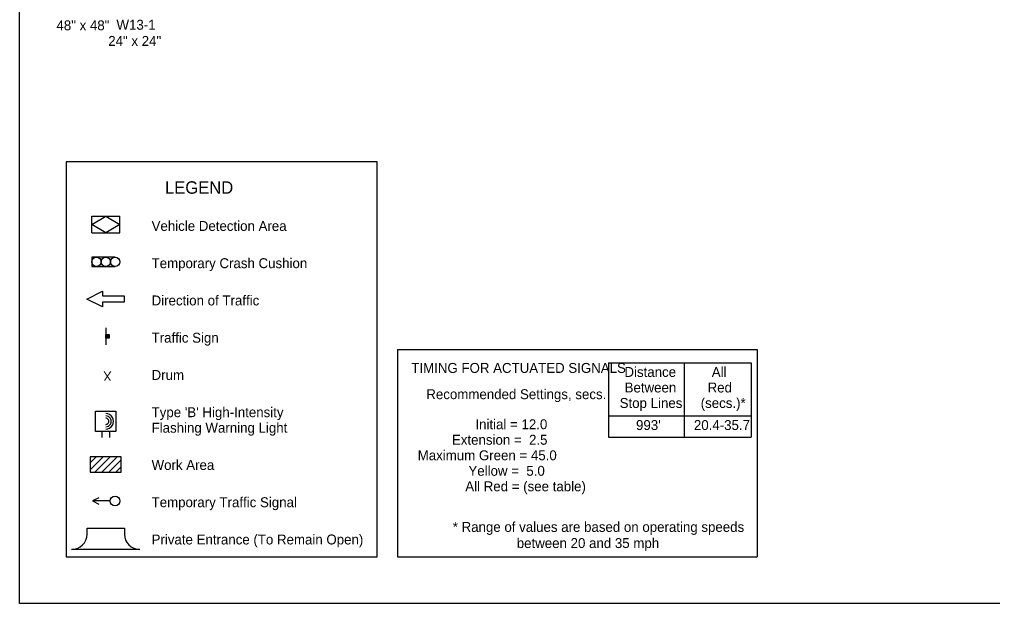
# Model space of a CAD drawing. Extents: x -2134934 to -2127057, y -2139046 to -2137036.
# Drawn here: x -2134934 to -2133366, y -2139046 to -2138105 of the extents above; entities that cross this region are included whole.
import ezdxf

# ---------------------------------------------------------------- set-up
doc = ezdxf.new("R2010")
doc.units = 0
for name, color, linetype in [('Barrier', 7, 'Continuous'), ('BridgeSuperStructureExisting', 7, 'Continuous'), ('Default', 7, 'Continuous'), ('dsnStdLabel', 7, 'Continuous'), ('dsnTextFinalPlan', 7, 'Continuous')]:
    doc.layers.add(name, color=color, linetype=linetype)

msp = doc.modelspace()

# ---------------------------------------------------------------- linework, layer by layer
at = {"layer": 'BridgeSuperStructureExisting'}
for p, q in [((-2134817.8, -2138449.1), (-2134817.8, -2138422.1)), ((-2134817.8, -2138422.1), (-2134772.8, -2138422.1)), ((-2134772.8, -2138449.1), (-2134772.8, -2138422.1)), ((-2134817.8, -2138449.1), (-2134772.8, -2138449.1)), ((-2134817.8, -2138488.1), (-2134817.8, -2138503.1)), ((-2134780.3, -2138488.1), (-2134817.8, -2138488.1)), ((-2134817.8, -2138503.1), (-2134780.3, -2138503.1)), ((-2134795.3, -2138601.9), (-2134795.3, -2138629.4)), ((-2134794.9, -2138618.4), (-2134794.9, -2138612.8)), ((-2134794.6, -2138612.8), (-2134794.6, -2138618.4)), ((-2134794.3, -2138618.4), (-2134794.3, -2138612.8)), ((-2134794.1, -2138612.8), (-2134794.1, -2138618.4)), ((-2134793.9, -2138618.4), (-2134793.9, -2138612.8)), ((-2134793.6, -2138612.8), (-2134793.6, -2138618.4)), ((-2134793.3, -2138618.4), (-2134793.3, -2138612.8)), ((-2134793, -2138612.8), (-2134793, -2138618.4)), ((-2134792.8, -2138618.4), (-2134792.8, -2138612.8)), ((-2134792.5, -2138612.8), (-2134792.5, -2138618.4)), ((-2134792.1, -2138618.4), (-2134792.1, -2138612.8)), ((-2134791.7, -2138612.8), (-2134791.7, -2138618.4)), ((-2134791.5, -2138618.4), (-2134791.5, -2138612.8)), ((-2134791.1, -2138612.8), (-2134791, -2138618.4)), ((-2134790.8, -2138618.4), (-2134790.8, -2138612.8)), ((-2134790.5, -2138612.8), (-2134790.5, -2138618.4)), ((-2134790.3, -2138618.4), (-2134790.3, -2138612.8)), ((-2134790, -2138612.8), (-2134790, -2138618.4)), ((-2134325, -2138636.9), (-2134325, -2138970.9)), ((-2134325, -2138636.9), (-2133745, -2138636.9)), ((-2133745, -2138636.9), (-2133745, -2138970.9)), ((-2134801.6, -2138768.8), (-2134801.6, -2138778.8)), ((-2134789.1, -2138768.8), (-2134789.1, -2138778.8)), ((-2134820.3, -2138830.5), (-2134799.3, -2138809.5)), ((-2134820.3, -2138819.2), (-2134810.6, -2138809.5)), ((-2134813, -2138834.5), (-2134788, -2138809.5)), ((-2134801.7, -2138834.5), (-2134776.7, -2138809.5)), ((-2134790.4, -2138834.5), (-2134770.3, -2138814.5)), ((-2134779, -2138834.5), (-2134770.3, -2138825.8)), ((-2134788.2, -2138880.6), (-2134816.1, -2138880.6)), ((-2134740.3, -2138959), (-2134850.3, -2138959)), ((-2134325, -2138970.9), (-2133745, -2138970.9))]:
    msp.add_line(p, q, dxfattribs=at)
for points in [[(-2134859.4, -2138970.9), (-2134357.9, -2138970.9), (-2134357.9, -2138334.3), (-2134859.4, -2138334.3)], [(-2134765.6, -2138550.6), (-2134765.6, -2138560.6), (-2134800.6, -2138560.6), (-2134800.6, -2138568.1), (-2134825.6, -2138555.6), (-2134800.6, -2138543.1), (-2134800.6, -2138550.6)], [(-2134795.2, -2138618.4), (-2134795.2, -2138612.7), (-2134789.6, -2138612.7), (-2134789.6, -2138618.4)], [(-2134811.6, -2138768.8), (-2134811.6, -2138736.3), (-2134779.1, -2138736.3), (-2134779.1, -2138768.8)], [(-2134820.3, -2138834.5), (-2134770.3, -2138834.5), (-2134770.3, -2138809.5), (-2134820.3, -2138809.5)]]:
    msp.add_lwpolyline(points, close=True, dxfattribs=at)
for points in [[(-2134806.5, -2138875.7), (-2134816.5, -2138880.7), (-2134806.5, -2138885.7)], [(-2134825.3, -2138934), (-2134825.3, -2138924.5), (-2134765.3, -2138924.5), (-2134765.3, -2138934)]]:
    msp.add_lwpolyline(points, dxfattribs=at)
for centre, radius in [((-2134810.3, -2138495.6), 7.5), ((-2134810.3, -2138495.6), 7.5), ((-2134795.3, -2138495.6), 7.5), ((-2134795.3, -2138495.6), 7.5), ((-2134780.3, -2138495.6), 7.5), ((-2134780.3, -2138495.6), 7.5), ((-2134780.4, -2138880.9), 7.74)]:
    msp.add_circle(centre, radius, dxfattribs=at)
for centre, radius, start, end in [((-2134795.3, -2138752.5), 12.5, 269.4041, 90.5445), ((-2134795.3, -2138752.5), 12.5, 269.4041, 90.5445), ((-2134795.3, -2138752.5), 8.75, 269.4041, 90.5445), ((-2134795.3, -2138752.5), 5, 269.4041, 90.5445), ((-2134850.3, -2138934), 25, 270, 360), ((-2134740.3, -2138934), 25, 180, 270)]:
    msp.add_arc(centre, radius, start, end, dxfattribs=at)
at = {"layer": 'Default'}
msp.add_lwpolyline([(-2134934.4, -2137035.9), (-2131799.4, -2137035.9), (-2131799.4, -2139045.9), (-2134934.4, -2139045.9)], close=True, dxfattribs=at)
at = {"layer": 'dsnStdLabel'}
for p, q in [((-2133985, -2138658.5), (-2133985, -2138778)), ((-2133985, -2138658.5), (-2133755, -2138658.5)), ((-2133862.6, -2138658.5), (-2133862.6, -2138778)), ((-2133755, -2138658.5), (-2133755, -2138778)), ((-2133985, -2138743.5), (-2133755, -2138743.5)), ((-2133985, -2138778), (-2133755, -2138778))]:
    msp.add_line(p, q, dxfattribs=at)
at = {"layer": 'dsnTextFinalPlan'}
msp.add_lwpolyline([(-2134817.8, -2138435.6), (-2134795.3, -2138422.1), (-2134772.8, -2138435.6), (-2134795.3, -2138449.1)], close=True, dxfattribs=at)

# ---------------------------------------------------------------- texts
at = {"layer": 'Barrier'}
for s, p in [('48" x 48"', (-2134874.8, -2138122.7)), ('W13-1', (-2134778, -2138121.8)), ('24" x 24"', (-2134791.3, -2138147.8))]:
    msp.add_text(s, height=16, dxfattribs=at).set_placement(p)
at = {"layer": 'BridgeSuperStructureExisting'}
msp.add_text('X', height=15, rotation=180, dxfattribs=at).set_placement((-2134785.9, -2138672.2))
at = {"layer": 'dsnStdLabel'}
for s, height, p in [('LEGEND', 20, (-2134699.8, -2138385.9)), ('Vehicle Detection Area', 16, (-2134721.4, -2138445.8)), ('Temporary Crash Cushion', 16, (-2134721.4, -2138505.8)), ('Direction of Traffic', 16, (-2134721.4, -2138565.8)), ('Traffic Sign', 16, (-2134721.4, -2138625.8)), ('Drum', 16, (-2134721.4, -2138685.8)), ('TIMING FOR ACTUATED SIGNALS', 16, (-2134302.7, -2138674.5)), ('Distance', 16, (-2133959.1, -2138681)), ('All', 16, (-2133818.3, -2138681)), ('Red', 16, (-2133825, -2138706)), ('Recommended Settings, secs.', 16, (-2134278.5, -2138716.8)), ('Between', 16, (-2133958.8, -2138706)), ('Stop Lines', 16, (-2133966.8, -2138731)), (' (secs.)*', 16, (-2133842.1, -2138731)), ("Type 'B' High-Intensity", 16, (-2134721.4, -2138745.8)), ('Initial = 12.0', 16, (-2134199.4, -2138765.2)), ("993'", 16, (-2133940.4, -2138766.5)), ('20.4-35.7', 16, (-2133847.1, -2138766.5)), ('Flashing Warning Light', 16, (-2134721.4, -2138770.8)), ('Extension =  2.5', 16, (-2134237.2, -2138790.2)), ('Maximum Green = 45.0', 16, (-2134292.4, -2138815.2)), ('Work Area', 16, (-2134721.4, -2138830.8)), ('Yellow =  5.0', 16, (-2134210.6, -2138840.2)), ('All Red = (see table)', 16, (-2134215.7, -2138865.2)), ('Temporary Traffic Signal', 16, (-2134721.4, -2138890.8)), ('* Range of values are based on operating speeds', 16, (-2134235.9, -2138930.6)), ('Private Entrance (To Remain Open)', 16, (-2134721.4, -2138950.8)), ('between 20 and 35 mph', 16, (-2134132.7, -2138956.6))]:
    msp.add_text(s, height=height, dxfattribs=at).set_placement(p)

doc.saveas('drawing.dxf')
